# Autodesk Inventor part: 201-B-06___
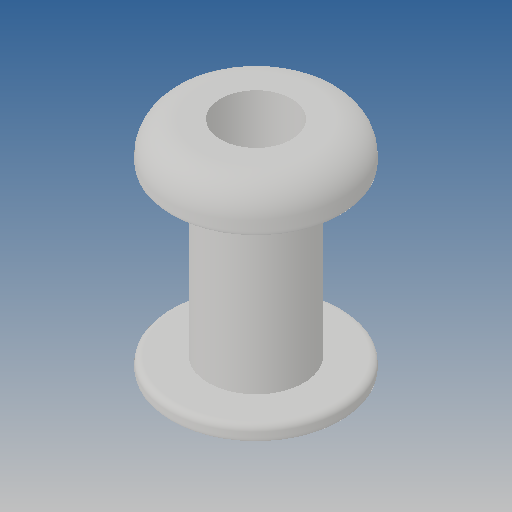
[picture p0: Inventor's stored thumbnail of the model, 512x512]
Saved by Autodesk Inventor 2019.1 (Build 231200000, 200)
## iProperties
Created: 2010-06
Part Number: 201-B-06___
Material: Ogólny
Document SubType Name: Modeling
Designer: CADENGINEERING4
Density: 1 g/cm^3
Appearance: Domyślna
Author: CADENGINEERING4
Revision Number: ANY
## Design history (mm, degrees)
feature "NONE"
node "Bryła1"
